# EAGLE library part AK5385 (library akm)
Audio ADC 114dB, 192kHz, 24-Bit, 2ch, Delta Sigma
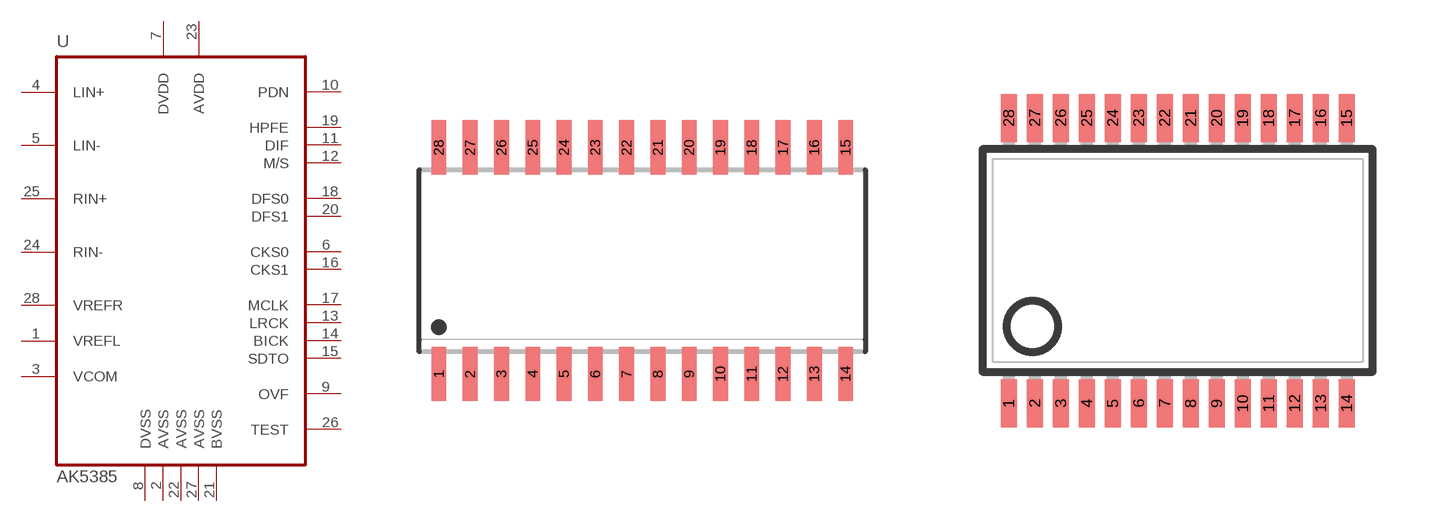
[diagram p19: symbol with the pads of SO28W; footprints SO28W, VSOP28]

Designator prefix U

## AK5385AVS  [SO28W]
1  VREFL  out
2  AVSS  pwr
3  VCOM  out
4  LIN+  in
5  LIN-  in
6  CKS0  in
7  DVDD  pwr
8  DVSS  pwr
9  OVF  out
10  PDN  in
11  DIF  in
12  M/S  in
13  LRCK
14  BICK
15  SDTO  out
16  CKS1  in
17  MCLK  in
18  DFS0  in
19  HPFE  in
20  DFS1  in
21  BVSS  pwr
22  AVSS1  pwr
23  AVDD  pwr
24  RIN-  in
25  RIN+  in
26  TEST  in
27  AVSS2  pwr
28  VREFR  out

## AK5385AVF  [VSOP28]
Pads as for SO28W

## Footprint SO28W (pad centres in mm)
SMALL OUTLINE INTEGRATED CIRCUIT wide body 7.5 mm/JEDEC MO-119AB
smd 0.6 x 2.2: 1 -8.255,-4.6; 2 -6.985,-4.6; 3 -5.715,-4.6; 4 -4.445,-4.6; 5 -3.175,-4.6; 6 -1.905,-4.6; 7 -0.635,-4.6; 8 0.635,-4.6; 9 1.905,-4.6; 10 3.175,-4.6; 11 4.445,-4.6; 12 5.715,-4.6; 13 6.985,-4.6; 14 8.255,-4.6; 15 8.255,4.6; 16 6.985,4.6; 17 5.715,4.6; 18 4.445,4.6; 19 3.175,4.6; 20 1.905,4.6; 21 0.635,4.6; 22 -0.635,4.6; 23 -1.905,4.6; 24 -3.175,4.6; 25 -4.445,4.6; 26 -5.715,4.6; 27 -6.985,4.6; 28 -8.255,4.6

## Footprint VSOP28 (pad centres in mm)
VSOP28 9.8 x 5.6 mm, pitch .65 mm
smd 0.4 x 1.2: 1 -4.225,-3.57; 2 -3.575,-3.57; 3 -2.925,-3.57; 4 -2.275,-3.57; 5 -1.625,-3.57; 6 -0.975,-3.57; 7 -0.325,-3.57; 8 0.325,-3.57; 9 0.975,-3.57; 10 1.625,-3.57; 11 2.275,-3.57; 12 2.925,-3.57; 13 3.575,-3.57; 14 4.225,-3.57; 15 4.225,3.57; 16 3.575,3.57; 17 2.925,3.57; 18 2.275,3.57; 19 1.625,3.57; 20 0.975,3.57; 21 0.325,3.57; 22 -0.325,3.57; 23 -0.975,3.57; 24 -1.625,3.57; 25 -2.275,3.57; 26 -2.925,3.57; 27 -3.575,3.57; 28 -4.225,3.57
